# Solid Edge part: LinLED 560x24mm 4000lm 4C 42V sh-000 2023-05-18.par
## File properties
Author: jaroslaw.przewlocki
Template: iso metric part.par
Last saved by: jaroslaw.przewlocki
Revision: 3
Application: Solid Edge
Gęstość: 0,000 kg/m^3
Dokładność: 0,990
Username: jaroslaw.przewlocki
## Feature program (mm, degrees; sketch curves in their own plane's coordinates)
body "unnamed Body 1"
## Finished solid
Body 1: solid body, 2802 faces, 7264 edges, 4728 vertices.
  Faces by surface: plane 2204, cylinder 286, torus 128, cone 100, spline 52, sphere 32
  Edges by curve: line 5996, curve on surface 712, circle 352, ellipse 132, spline 72
Bounding box of the edges (mm; curved faces can reach further): 559.600 x 24.000 x 4.450, from (-279.8, -12, 0) to (279.8, 12, 4.45).
Cylindrical faces by radius (mm): R0.2 x92, R0.2169 x12, R0.25 x36, R0.3373 x12, R0.4 x16, R0.4006 x4, R0.4008 x4, R0.525 x4, R0.6 x40, R1 x20, R1.1 x8, R1.1989 x4, R1.199 x4, R1.2 x20, R2.15 x10
Conical faces (half-angle, radius in mm at the cone's reference point): 0.398 deg R1.1964 x4, 0.4493 deg R1.1964 x4, 0.4746 deg R1.1948 x4, 0.4758 deg R1.1948 x4, 0.5 deg R0.5056 x8, 0.5 deg R1.0082 x8, 1 deg R0.5511 x4, 10 deg R0.2132 x8, 10 deg R0.4132 x8, 16.0099 deg R1.1053 x4, 16.1249 deg R1.1279 x4, 18.8604 deg R1.0669 x8, 19.5041 deg R0.5138 x4, 19.8244 deg R0.5099 x4, 27.363 deg R0.6214 x4, 40.6434 deg R0.5161 x4, 43.3309 deg R0.4892 x4, 45 deg R0.575 x4, 45 deg R0.625 x8
Toroidal faces (ring radius, tube radius in mm): R0.0958 r0.3997 x8, R0.1076 r0.4 x4, R0.1101 r0.4001 x4, R0.1217 r0.4 x4, R0.1234 r0.4 x4, R0.1626 r0.228 x4, R0.1634 r0.2287 x4, R0.3287 r0.2001 x4, R0.3684 r0.2151 x4, R0.3703 r0.4 x4, R0.3818 r0.2 x8, R0.4166 r0.3983 x4, R0.5981 r0.197 x4, R0.5982 r0.197 x4, R0.6009 r0.3968 x4, R0.6009 r0.3969 x4, R0.6227 r0.2 x4, R0.6235 r0.2 x4, R0.8 r0.2 x8, R0.8522 r0.3 x4, R0.9002 r0.2 x4, R0.9018 r0.2 x4, R0.9197 r0.223 x4, R0.9365 r0.2 x4, R0.9663 r0.2263 x4, R0.9665 r0.2263 x4, R1.429 r1.2 x4, R1.8741 r0.2175 x4, R1.9007 r0.2 x4
Spherical faces by radius (mm): R0.2 x24, R0.6 x8
Planar faces by outward normal: +x 261, +y 263, +z 385, -x 261, -y 269, -z 17, oblique 748
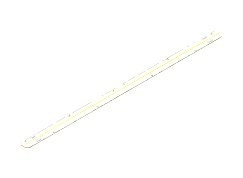
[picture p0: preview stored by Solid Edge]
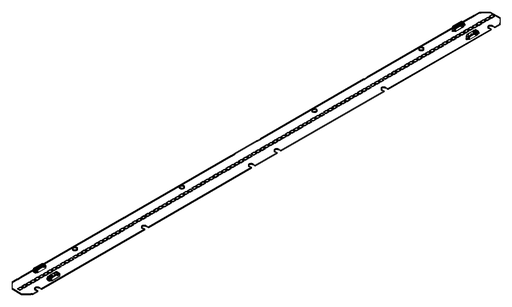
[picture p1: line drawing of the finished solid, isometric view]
